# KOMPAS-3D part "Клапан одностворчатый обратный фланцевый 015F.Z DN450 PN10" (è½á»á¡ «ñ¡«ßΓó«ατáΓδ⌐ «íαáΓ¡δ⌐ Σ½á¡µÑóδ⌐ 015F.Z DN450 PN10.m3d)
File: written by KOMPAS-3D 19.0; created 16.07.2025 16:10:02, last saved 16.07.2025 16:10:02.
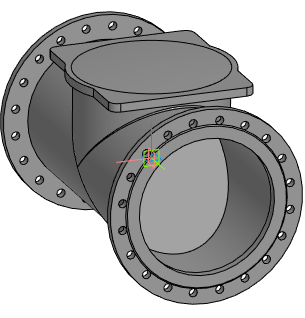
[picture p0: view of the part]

Document properties: Полное имя файла: E:\Dendor Работа Сачек\3D для проектировщиков\5.4 Тип 015F.Z. Клапан одностворчатый обратный фланцевый\stp_Клапан одностворчатый обратный фланцевый 015F.Z PN10_16\Клапан одностворчатый обратный фланцевый 015F.Z DN450 PN10.m3d

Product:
- Part/product: Клапан одностворчатый обратный фланцевый 015F.Z DN450 PN10

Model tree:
1. Операция без истории:1  (labels: Клапан одностворчатый обратный фланцевый 015F.Z DN450 PN10)
2. Операция без истории:2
